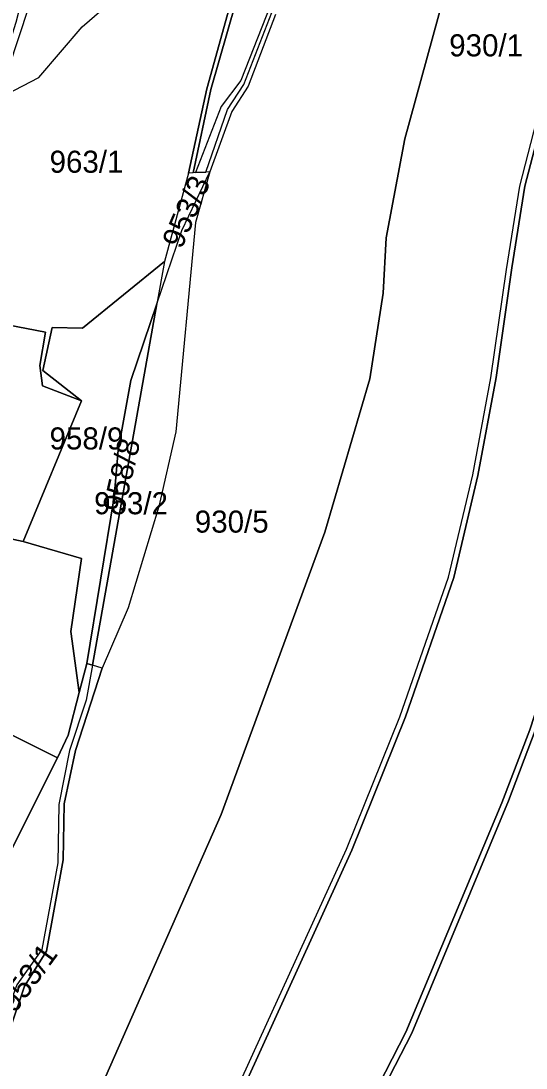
# Model space of a CAD drawing. Extents: x -623250 to -619626, y -1079612 to -1075424.
# Drawn here: x -621687.6 to -621458.8, y -1079113.5 to -1078639.2 of the extents above; entities that cross this region are included whole.
import ezdxf

# ---------------------------------------------------------------- set-up
doc = ezdxf.new("R2010")
doc.units = 0
doc.layers.add('Parcela nároku', color=7, linetype='Continuous')
doc.layers.add('Parcelní číslo', color=7, linetype='Continuous')

msp = doc.modelspace()

# ---------------------------------------------------------------- linework, layer by layer
at = {"layer": 'Parcela nároku'}
for points in [[(-621160.87, -1078150.94), (-621195.01, -1078232.61), (-621206.9, -1078269.15), (-621229.75, -1078321.25), (-621243.59, -1078348.94), (-621300.37, -1078450.53), (-621348.82, -1078539.66), (-621362.78, -1078573.74), (-621403.68, -1078689.33), (-621411.98, -1078716.86), (-621415.88, -1078735.94), (-621430.26, -1078854.44), (-621439.94, -1078902.91), (-621448.54, -1078933.98), (-621457.03, -1078960.26), (-621469.72, -1078993.33), (-621513.27, -1079097.24), (-621553.12, -1079174.98)], [(-621623.35, -1079196.85), (-621581.79, -1079105.62), (-621540.15, -1079014.34), (-621516.01, -1078954.42), (-621493.87, -1078891.2), (-621482.89, -1078844.86), (-621474.78, -1078800.9), (-621467.65, -1078751.76), (-621461.59, -1078713.98), (-621443.98, -1078645.43), (-621421.65, -1078575.29), (-621395.74, -1078510.7), (-621328.21, -1078383.31), (-621285.96, -1078302.34), (-621260.27, -1078247.26), (-621226.36, -1078165.63)], [(-621623.35, -1079196.85), (-621581.79, -1079105.62), (-621540.15, -1079014.34), (-621516.01, -1078954.42), (-621493.87, -1078891.2), (-621482.89, -1078844.86), (-621474.78, -1078800.9), (-621467.65, -1078751.76), (-621461.59, -1078713.98), (-621443.98, -1078645.43), (-621421.65, -1078575.29), (-621395.74, -1078510.7), (-621328.21, -1078383.31), (-621285.96, -1078302.34), (-621260.27, -1078247.26), (-621226.36, -1078165.63)], [(-621620.64, -1079196.85), (-621537.78, -1079014.84), (-621513.43, -1078954.49), (-621491.51, -1078891.26), (-621480.64, -1078845.11), (-621472.29, -1078800.7), (-621465.28, -1078751.09), (-621459.35, -1078714.06), (-621441.33, -1078645.33), (-621418.85, -1078575.15), (-621393.44, -1078511.85), (-621326.06, -1078385.04), (-621282.99, -1078303), (-621257.7, -1078248.55), (-621223.28, -1078165.91)], [(-621223.28, -1078165.91), (-621257.7, -1078248.55), (-621282.99, -1078303), (-621326.06, -1078385.04), (-621393.44, -1078511.85), (-621418.85, -1078575.15), (-621441.33, -1078645.33), (-621459.35, -1078714.06), (-621465.28, -1078751.09), (-621472.29, -1078800.7), (-621480.64, -1078845.11), (-621491.51, -1078891.26), (-621513.43, -1078954.49), (-621537.78, -1079014.84), (-621620.64, -1079196.85)], [(-621246.01, -1078185.49), (-621266.68, -1078212.76), (-621275.63, -1078229.25), (-621289.76, -1078235.93), (-621307, -1078240.79), (-621324.7, -1078249.3), (-621330.24, -1078260.55), (-621336.49, -1078264.69), (-621356.58, -1078308.26), (-621371.42, -1078334.2), (-621436.88, -1078461.43), (-621461.05, -1078515.35), (-621472.93, -1078545.76), (-621482.56, -1078579.03), (-621483.31, -1078581.78), (-621513.7, -1078692.54), (-621522.18, -1078737.53), (-621523.53, -1078762.49), (-621529.55, -1078801.39), (-621550, -1078870.86), (-621596.99, -1078998.76), (-621655.34, -1079131.2)], [(-621553.12, -1079174.98), (-621513.27, -1079097.24), (-621469.72, -1078993.33), (-621457.03, -1078960.26), (-621448.54, -1078933.98), (-621439.94, -1078902.91), (-621430.26, -1078854.44), (-621415.88, -1078735.94), (-621411.98, -1078716.86), (-621403.68, -1078689.33), (-621362.78, -1078573.74), (-621348.82, -1078539.66), (-621300.37, -1078450.53), (-621243.59, -1078348.94), (-621229.75, -1078321.25), (-621206.9, -1078269.15), (-621191.82, -1078231.8), (-621175.34, -1078191.16)], [(-621176.77, -1078204.28), (-621203.04, -1078268.81), (-621226.41, -1078321.97), (-621240.19, -1078349.74), (-621297.32, -1078451.47), (-621345.37, -1078541.61), (-621359.45, -1078574.28), (-621400.31, -1078690.19), (-621408.59, -1078716.87), (-621412.58, -1078735.75), (-621427.47, -1078854.66), (-621437.16, -1078902.52), (-621446.15, -1078934.09), (-621454.65, -1078960.57), (-621466.72, -1078992.45), (-621510.48, -1079097.75), (-621550.74, -1079175.59)], [(-621550.74, -1079175.59), (-621510.48, -1079097.75), (-621466.72, -1078992.45), (-621454.65, -1078960.57), (-621446.15, -1078934.09), (-621437.16, -1078902.52), (-621427.47, -1078854.66), (-621412.58, -1078735.75), (-621408.59, -1078716.87), (-621400.31, -1078690.19), (-621359.45, -1078574.28), (-621345.37, -1078541.61), (-621297.32, -1078451.47), (-621240.19, -1078349.74), (-621226.41, -1078321.97), (-621203.04, -1078268.81), (-621176.77, -1078204.28)], [(-621655.34, -1079131.2), (-621596.99, -1078998.76), (-621550, -1078870.86), (-621529.55, -1078801.39), (-621523.53, -1078762.49), (-621522.18, -1078737.53), (-621513.7, -1078692.54), (-621483.31, -1078581.78)], [(-621684.21, -1078633.08), (-621697.9, -1078674.4), (-621700.7, -1078674.01), (-621689.88, -1078639.73), (-621682.64, -1078612.21)], [(-621565.04, -1078607.81), (-621588, -1078666.16), (-621596.96, -1078677.93), (-621608.54, -1078707.92), (-621603.88, -1078707.66), (-621594.09, -1078679.26), (-621586.67, -1078667.99), (-621573.93, -1078635.37)], [(-621572.26, -1078636.28), (-621584.71, -1078668.69), (-621592.06, -1078680.24), (-621602.02, -1078707.55), (-621603.88, -1078707.66), (-621594.09, -1078679.26), (-621586.67, -1078667.99), (-621573.93, -1078635.37)], [(-621572.26, -1078636.28), (-621584.71, -1078668.69), (-621592.06, -1078680.24), (-621602.02, -1078707.55), (-621608.59, -1078730.53), (-621617.46, -1078825.31), (-621625.18, -1078859.11), (-621639.04, -1078905.08), (-621650.82, -1078932.47), (-621662.97, -1078969.66), (-621668.08, -1078993.89), (-621668.45, -1079019.15), (-621676.11, -1079060.58), (-621685.97, -1079076.42), (-621698.06, -1079111.98), (-621697.69, -1079138.49)]]:
    msp.add_lwpolyline(points, dxfattribs=at)
for points in [[(-621561.49, -1078549.39), (-621549.33, -1078518.46), (-621540.21, -1078516.17), (-621501.89, -1078479.4), (-621536.85, -1078560.1), (-621565.04, -1078607.81), (-621588, -1078666.16), (-621596.96, -1078677.93), (-621608.54, -1078707.92), (-621609.68, -1078707.98), (-621601.6, -1078670.24), (-621590.34, -1078630.91)], [(-621551.69, -1078519.05), (-621549.33, -1078518.46), (-621561.49, -1078549.39), (-621590.34, -1078630.91), (-621601.6, -1078670.24), (-621609.68, -1078707.98), (-621611.72, -1078708.1), (-621603.36, -1078669.93), (-621592.52, -1078630.82), (-621563.27, -1078549.01)], [(-621659.89, -1078641.88), (-621634.19, -1078619.47), (-621563.27, -1078549.01), (-621592.52, -1078630.82), (-621603.36, -1078669.93), (-621611.72, -1078708.1), (-621622.67, -1078748.23), (-621659.71, -1078778.43), (-621673.47, -1078778.15), (-621677.73, -1078797.56), (-621660.27, -1078811.32), (-621677.88, -1078804.44), (-621679.12, -1078795.35), (-621676.5, -1078780.22), (-621707.18, -1078774.3), (-621699.61, -1078733.28), (-621701.12, -1078697.21), (-621697.9, -1078674.4), (-621679.48, -1078664.79)], [(-621684.21, -1078633.08), (-621697.9, -1078674.4), (-621679.48, -1078664.79), (-621659.89, -1078641.88), (-621634.19, -1078619.47), (-621628.01, -1078579.6)], [(-621614.8, -1078734.07), (-621602.02, -1078707.55), (-621608.59, -1078730.53), (-621617.46, -1078825.31), (-621625.18, -1078859.11), (-621639.04, -1078905.08), (-621650.82, -1078932.47), (-621655.27, -1078931.11), (-621626.08, -1078767.34)], [(-621609.68, -1078707.98), (-621611.72, -1078708.1), (-621622.67, -1078748.23), (-621626.08, -1078767.34), (-621614.8, -1078734.07), (-621602.02, -1078707.55), (-621603.88, -1078707.66), (-621608.54, -1078707.92)], [(-621673.47, -1078778.15), (-621659.71, -1078778.43), (-621622.67, -1078748.23), (-621626.08, -1078767.34), (-621637.87, -1078802.14), (-621643.62, -1078833.6), (-621645.47, -1078854.83), (-621657.87, -1078930.32), (-621661.27, -1078943.44), (-621664.99, -1078915.82), (-621660.21, -1078882.79), (-621686.68, -1078874.96), (-621660.27, -1078811.32), (-621677.73, -1078797.56)], [(-621643.62, -1078833.6), (-621637.87, -1078802.14), (-621626.08, -1078767.34), (-621655.27, -1078931.11), (-621657.87, -1078930.32), (-621645.47, -1078854.83)], [(-621727.78, -1078840.72), (-621707.18, -1078774.3), (-621676.5, -1078780.22), (-621679.12, -1078795.35), (-621677.88, -1078804.44), (-621660.27, -1078811.32), (-621686.68, -1078874.96), (-621697.32, -1078872.82), (-621702.97, -1078871.55), (-621717.87, -1078879.58), (-621750.95, -1078902.37)], [(-621750.95, -1078902.37), (-621697.32, -1078872.82), (-621686.68, -1078874.96), (-621660.21, -1078882.79), (-621664.99, -1078915.82), (-621661.27, -1078943.44), (-621666.29, -1078962.8), (-621671.09, -1078973.07), (-621764.15, -1078926.59)], [(-621805.98, -1079012.11), (-621781.51, -1078959.58), (-621764.15, -1078926.59), (-621671.09, -1078973.07), (-621713.64, -1079057.74)], [(-621671.09, -1078973.07), (-621666.29, -1078962.8), (-621661.27, -1078943.44), (-621657.87, -1078930.32), (-621655.27, -1078931.11), (-621658.1, -1078946.96), (-621665.65, -1078969.71), (-621670.5, -1078994.1), (-621670.91, -1079020.63), (-621678.22, -1079059.82), (-621689.52, -1079075.82), (-621702.49, -1079110.81), (-621702.61, -1079138.31), (-621715.75, -1079175.17), (-621727.1, -1079196.04), (-621770.3, -1079174.14), (-621761.6, -1079147.11), (-621748.68, -1079122.32), (-621713.64, -1079057.74)], [(-621678.22, -1079059.82), (-621689.52, -1079075.82), (-621702.49, -1079110.81), (-621702.61, -1079138.31), (-621715.75, -1079175.17), (-621727.1, -1079196.04), (-621720.64, -1079199.22), (-621708.75, -1079176.95), (-621697.69, -1079138.49), (-621698.06, -1079111.98), (-621685.97, -1079076.42), (-621676.11, -1079060.58), (-621668.45, -1079019.15), (-621668.08, -1078993.89), (-621662.97, -1078969.66), (-621650.82, -1078932.47), (-621655.27, -1078931.11), (-621658.1, -1078946.96), (-621665.65, -1078969.71), (-621670.5, -1078994.1), (-621670.91, -1079020.63)]]:
    msp.add_lwpolyline(points, close=True, dxfattribs=at)

# ---------------------------------------------------------------- texts
at = {"layer": 'Parcelní číslo'}
for s, p in [('930/1', (-621493.63, -1078655.26)), ('963/1', (-621674.67, -1078707.98)), ('958/9', (-621674.68, -1078833.33)), ('953/2', (-621654.5, -1078862.68)), ('930/5', (-621608.88, -1078871))]:
    msp.add_text(s, height=10, dxfattribs=at).set_placement(p)
for s, rotation, p in [('953/3', 66.5393, (-621614.91, -1078742.92)), ('958/8', 76.9638, (-621641.05, -1078862.37)), ('953/1', 53.8754, (-621690.27, -1079088.98))]:
    msp.add_text(s, height=10, rotation=rotation, dxfattribs=at).set_placement(p)

doc.saveas('drawing.dxf')
